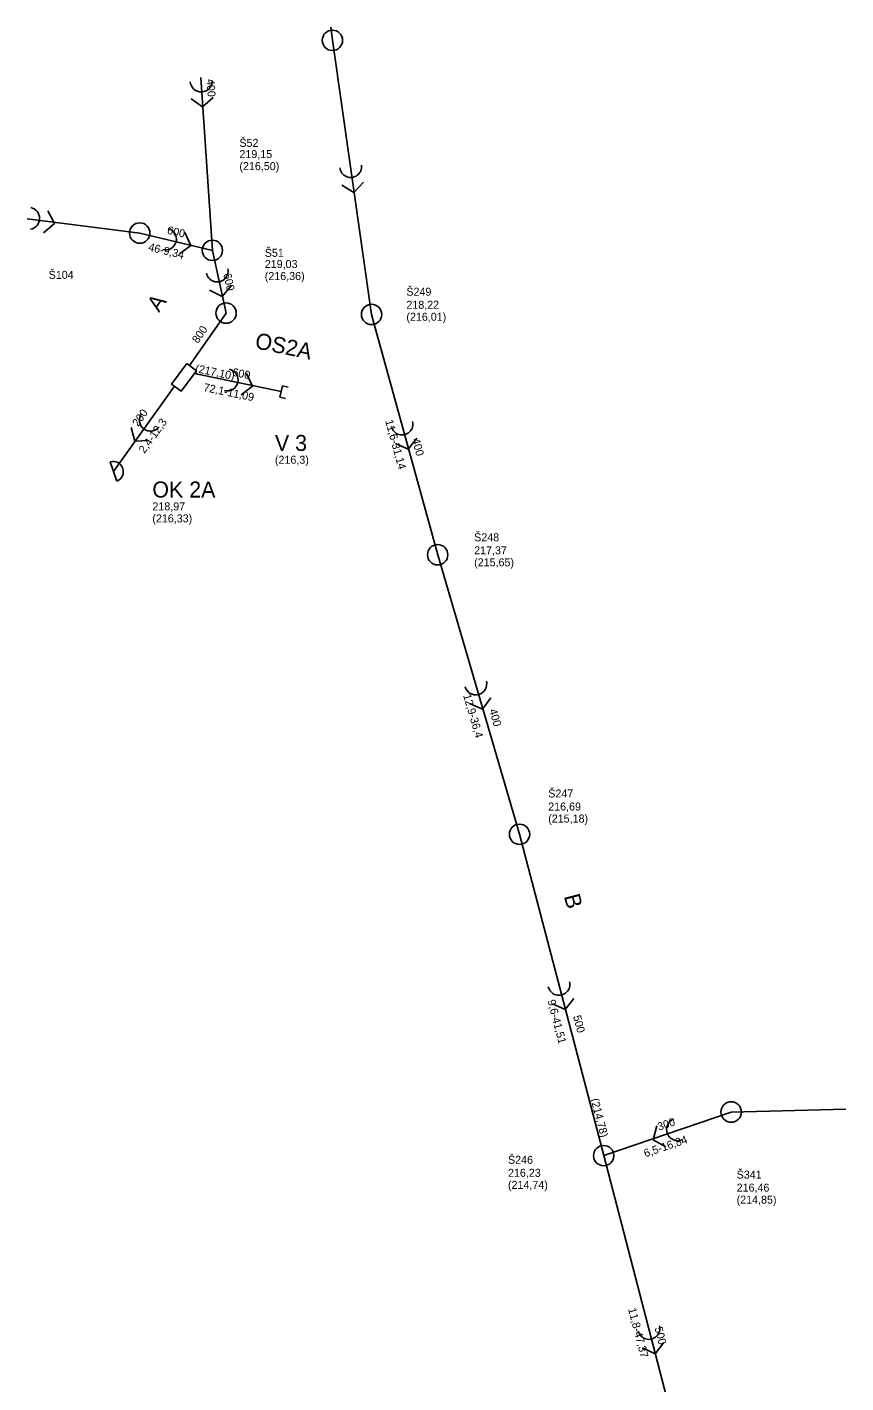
# Model space of a CAD drawing. Extents: x -569540 to -569072, y -1179643 to -1178245.
# Drawn here: x -569183.2 to -569080.9, y -1178414 to -1178244.5 of the extents above; entities that cross this region are included whole.
import ezdxf

# ---------------------------------------------------------------- set-up
doc = ezdxf.new("R2010")
doc.units = 0
for name, color, linetype in [('Vrstva 1', 7, 'Continuous'), ('Vrstva 15', 7, 'Continuous'), ('Vrstva 21', 7, 'Continuous'), ('Vrstva 29', 7, 'Continuous'), ('Vrstva 31', 7, 'Continuous'), ('Vrstva 32', 7, 'Continuous'), ('Vrstva 35', 7, 'Continuous'), ('Vrstva 41', 7, 'Continuous'), ('Vrstva 44', 7, 'Continuous'), ('Vrstva 45', 7, 'Continuous'), ('Vrstva 56', 7, 'Continuous'), ('Vrstva 57', 7, 'Continuous')]:
    doc.layers.add(name, color=color, linetype=linetype)

# ---------------------------------------------------------------- blocks, each defined once
blk = doc.blocks.new('100')
at = {"layer": 'Vrstva 1'}
blk.add_circle((0, 0), 1.27, dxfattribs=at)
blk = doc.blocks.new('96')
at = {"layer": 'Vrstva 1'}
for p, q in [((0, 0.72), (0, -0.72)), ((0, 0.72), (0.72, 0.72)), ((0.72, -0.72), (0, -0.72))]:
    blk.add_line(p, q, dxfattribs=at)
blk = doc.blocks.new('91')
at = {"layer": 'Vrstva 1'}
blk.add_lwpolyline([(0.79, 1.37), (1.89, 0), (0.79, -1.38)], dxfattribs=at)
blk.add_arc((-1.37, 0), 1.37, 270, 90, dxfattribs=at)
blk = doc.blocks.new('86')
at = {"layer": 'Vrstva 1'}
blk.add_lwpolyline([(0.79, 1.37), (1.89, 0), (0.79, -1.38)], dxfattribs=at)
blk.add_arc((-1.37, 0), 1.37, 270, 90, dxfattribs=at)

msp = doc.modelspace()

# ---------------------------------------------------------------- linework, layer by layer
at = {"layer": 'Vrstva 15'}
for p, q in [((-569145.24, -1178244.54), (-569145.04, -1178246.19)), ((-569145.04, -1178246.19), (-569140.14, -1178280.45)), ((-569161.49, -1178250.84), (-569160.04, -1178272.44)), ((-569183.2, -1178268.52), (-569169.12, -1178270.28)), ((-569169.12, -1178270.28), (-569160.04, -1178272.44)), ((-569160.04, -1178272.44), (-569158.33, -1178280.28)), ((-569158.33, -1178280.28), (-569162.88, -1178286.85)), ((-569140.14, -1178280.45), (-569131.88, -1178310.48)), ((-569164.79, -1178289.42), (-569172.41, -1178300.06)), ((-569131.88, -1178310.48), (-569121.65, -1178345.42)), ((-569121.65, -1178345.42), (-569111.13, -1178385.58)), ((-569080.86, -1178379.76), (-569095.19, -1178380.13)), ((-569095.19, -1178380.13), (-569111.13, -1178385.58)), ((-569111.13, -1178385.58), (-569099.16, -1178431.42))]:
    msp.add_line(p, q, dxfattribs=at)
at = {"layer": 'Vrstva 21'}
msp.add_line((-569162.29, -1178287.84), (-569151.44, -1178290.09), dxfattribs=at)
at = {"layer": 'Vrstva 29'}
msp.add_lwpolyline([(-569172.81, -1178298.88), (-569171.99, -1178301.29)], dxfattribs=at)
msp.add_arc((-569172.44, -1178300.1), 1.27, 290.7063, 107.0524, dxfattribs=at)
at = {"layer": 'Vrstva 31'}
msp.add_lwpolyline([(-569163.23, -1178286.59), (-569165.16, -1178289.15), (-569163.96, -1178290.05), (-569162.03, -1178287.49), (-569163.23, -1178286.59)], dxfattribs=at)
at = {"layer": 'Vrstva 41'}
for points in [[(-569159.96, -1178253.35), (-569161.27, -1178254.52), (-569162.7, -1178253.5)], [(-569180.6, -1178267.51), (-569179.78, -1178269.08), (-569181.13, -1178270.23)]]:
    msp.add_lwpolyline(points, dxfattribs=at)
for centre, radius, start, end in [((-569161.44, -1178251.27), 1.37, 183.7359, 3), ((-569183.01, -1178268.45), 1.38, 280.4291, 78.8831)]:
    msp.add_arc(centre, radius, start, end, dxfattribs=at)

# ---------------------------------------------------------------- block references
at = {"layer": 'Vrstva 29'}
for p, xscale, yscale, rotation in [((-569145.04, -1178246.19), 1.000191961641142, 1.000191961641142, 97.08900113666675), ((-569169.12, -1178270.28), 1.0073309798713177, 1.007330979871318, 167.86109216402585), ((-569160.04, -1178272.44), 0.9999999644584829, 0.999999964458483, -140.99999893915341), ((-569158.33, -1178280.28), 0.9999999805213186, 0.9999999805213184, -100.99999941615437), ((-569140.14, -1178280.45), 0.999999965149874, 0.9999999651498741, 102.0000000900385), ((-569131.88, -1178310.48), 0.9999999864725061, 0.9999999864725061, 105.99999860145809), ((-569121.65, -1178345.42), 0.9999999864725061, 0.9999999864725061, 105.99999860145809), ((-569095.19, -1178380.13), 1.00837761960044, 1.00837761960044, -168.3736213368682), ((-569111.13, -1178385.58), 0.999999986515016, 0.9999999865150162, 105.00000012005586)]:
    msp.add_blockref('100', p, dxfattribs=dict(at, xscale=xscale, yscale=yscale, rotation=rotation))
at = {"layer": 'Vrstva 31', "xscale": 1.0028916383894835, "yscale": 1.0028916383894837, "rotation": -13.697207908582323}
msp.add_blockref('96', (-569151.44, -1178290.09), dxfattribs=at)
at = {"layer": 'Vrstva 41'}
for name, p, xscale, yscale, rotation in [('86', (-569142.59, -1178263.32), 1.000191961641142, 1.000191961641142, -82.91099886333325), ('91', (-569164.58, -1178271.36), 1.0009847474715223, 1.0009847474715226, -14.22432628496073), ('86', (-569159.18, -1178276.36), 0.9999999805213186, 0.9999999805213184, -79.00000058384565), ('86', (-569156.87, -1178288.97), 1.0028916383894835, 1.0028916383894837, -13.697207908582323), ('86', (-569168.61, -1178294.76), 0.9999999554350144, 0.9999999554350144, -126.99999920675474), ('86', (-569136.01, -1178295.47), 0.9999999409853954, 0.9999999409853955, -75.99999967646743), ('91', (-569126.76, -1178327.95), 0.999999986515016, 0.9999999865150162, -74.99999987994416), ('91', (-569116.39, -1178365.5), 0.9999999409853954, 0.9999999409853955, -75.99999967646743), ('86', (-569103.16, -1178382.85), 1.0335064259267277, 1.033506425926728, -156.95871849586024), ('91', (-569105.15, -1178408.5), 0.9999999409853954, 0.9999999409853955, -75.99999967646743)]:
    msp.add_blockref(name, p, dxfattribs=dict(at, xscale=xscale, yscale=yscale, rotation=rotation))

# ---------------------------------------------------------------- texts
at = {"layer": 'Vrstva 32'}
for s, height, p in [('V 3', 2, (-569152.22, -1178297.51)), ('(216,3)', 1, (-569152.22, -1178299.11)), ('OK 2A', 2, (-569167.54, -1178303.33)), ('218,97 ', 1, (-569167.54, -1178304.94)), ('(216,33)', 1, (-569167.54, -1178306.44))]:
    msp.add_text(s, height=height, dxfattribs=at).set_placement(p)
at = {"layer": 'Vrstva 35'}
for s, rotation, p in [('A', 55.3, (-569166.71, -1178280.27)), ('OS2A', 348.29, (-569154.82, -1178284.65)), ('B', 284.68, (-569116.11, -1178353.15))]:
    msp.add_text(s, height=2, rotation=rotation, dxfattribs=at).set_placement(p)
at = {"layer": 'Vrstva 44'}
for s, rotation, p in [('400', 273.84, (-569160.77, -1178251.06)), ('600', 346.6, (-569165.76, -1178270.36)), ('600', 282.27, (-569158.68, -1178275.4)), ('800', 55.3, (-569161.85, -1178284.14)), ('600', 348.29, (-569157.6, -1178288.1)), ('200', 54.38, (-569169.33, -1178294.55)), ('400', 285.38, (-569135.11, -1178296.08)), ('400', 286.32, (-569125.46, -1178329.9)), ('500', 284.68, (-569114.97, -1178368.17)), ('300', 18.88, (-569104.21, -1178382.48)), ('500', 284.63, (-569104.78, -1178407.13))]:
    msp.add_text(s, height=1, rotation=rotation, dxfattribs=at).set_placement(p)
at = {"layer": 'Vrstva 45'}
for s, rotation, p in [('46-9,34', 346.6, (-569168.11, -1178272.47)), ('(217,10)', 348.29, (-569162.25, -1178287.64)), ('72,1-11,09', 348.29, (-569161.21, -1178290.01)), ('2,4-12,3', 54.38, (-569168.52, -1178297.89)), ('11,6-31,14', 285.38, (-569138.45, -1178293.74)), ('12,9-36,4', 286.32, (-569128.71, -1178328.05)), ('9,6-41,51', 284.68, (-569118.17, -1178366.22)), ('(214,78)', 284.68, (-569112.76, -1178378.56)), ('6,5-16,84', 18.88, (-569105.92, -1178385.8)), ('11,8-47,37', 284.63, (-569108.09, -1178404.75))]:
    msp.add_text(s, height=1, rotation=rotation, dxfattribs=at).set_placement(p)
at = {"layer": 'Vrstva 56'}
for s, p in [('219,15 ', (-569156.66, -1178260.91)), ('(216,50)', (-569156.66, -1178262.41)), ('219,03 ', (-569153.49, -1178274.65)), ('(216,36)', (-569153.49, -1178276.15)), ('218,22 ', (-569135.79, -1178279.74)), ('(216,01)', (-569135.79, -1178281.24)), ('217,37 ', (-569127.32, -1178310.43)), ('(215,65)', (-569127.32, -1178311.93)), ('216,69 ', (-569118.06, -1178342.45)), ('(215,18)', (-569118.06, -1178343.95)), ('216,23 ', (-569123.09, -1178388.23)), ('(214,74)', (-569123.09, -1178389.73)), ('216,46 ', (-569094.51, -1178390.08)), ('(214,85)', (-569094.51, -1178391.58))]:
    msp.add_text(s, height=1, dxfattribs=at).set_placement(p)
at = {"layer": 'Vrstva 57'}
for s, p in [('Š52', (-569156.66, -1178259.51)), ('Š51', (-569153.49, -1178273.25)), ('Š104', (-569180.5, -1178276)), ('Š249', (-569135.79, -1178278.11)), ('Š248', (-569127.32, -1178308.8)), ('Š247', (-569118.06, -1178340.82)), ('Š246', (-569123.09, -1178386.6)), ('Š341', (-569094.51, -1178388.45))]:
    msp.add_text(s, height=1, dxfattribs=at).set_placement(p)

doc.saveas('drawing.dxf')
